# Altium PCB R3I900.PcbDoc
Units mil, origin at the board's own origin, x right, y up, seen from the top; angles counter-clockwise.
Board outline not stored, 2 copper layers (Top Layer, Bottom Layer); 27 components, 25 nets, 102 pads, 31 vias.
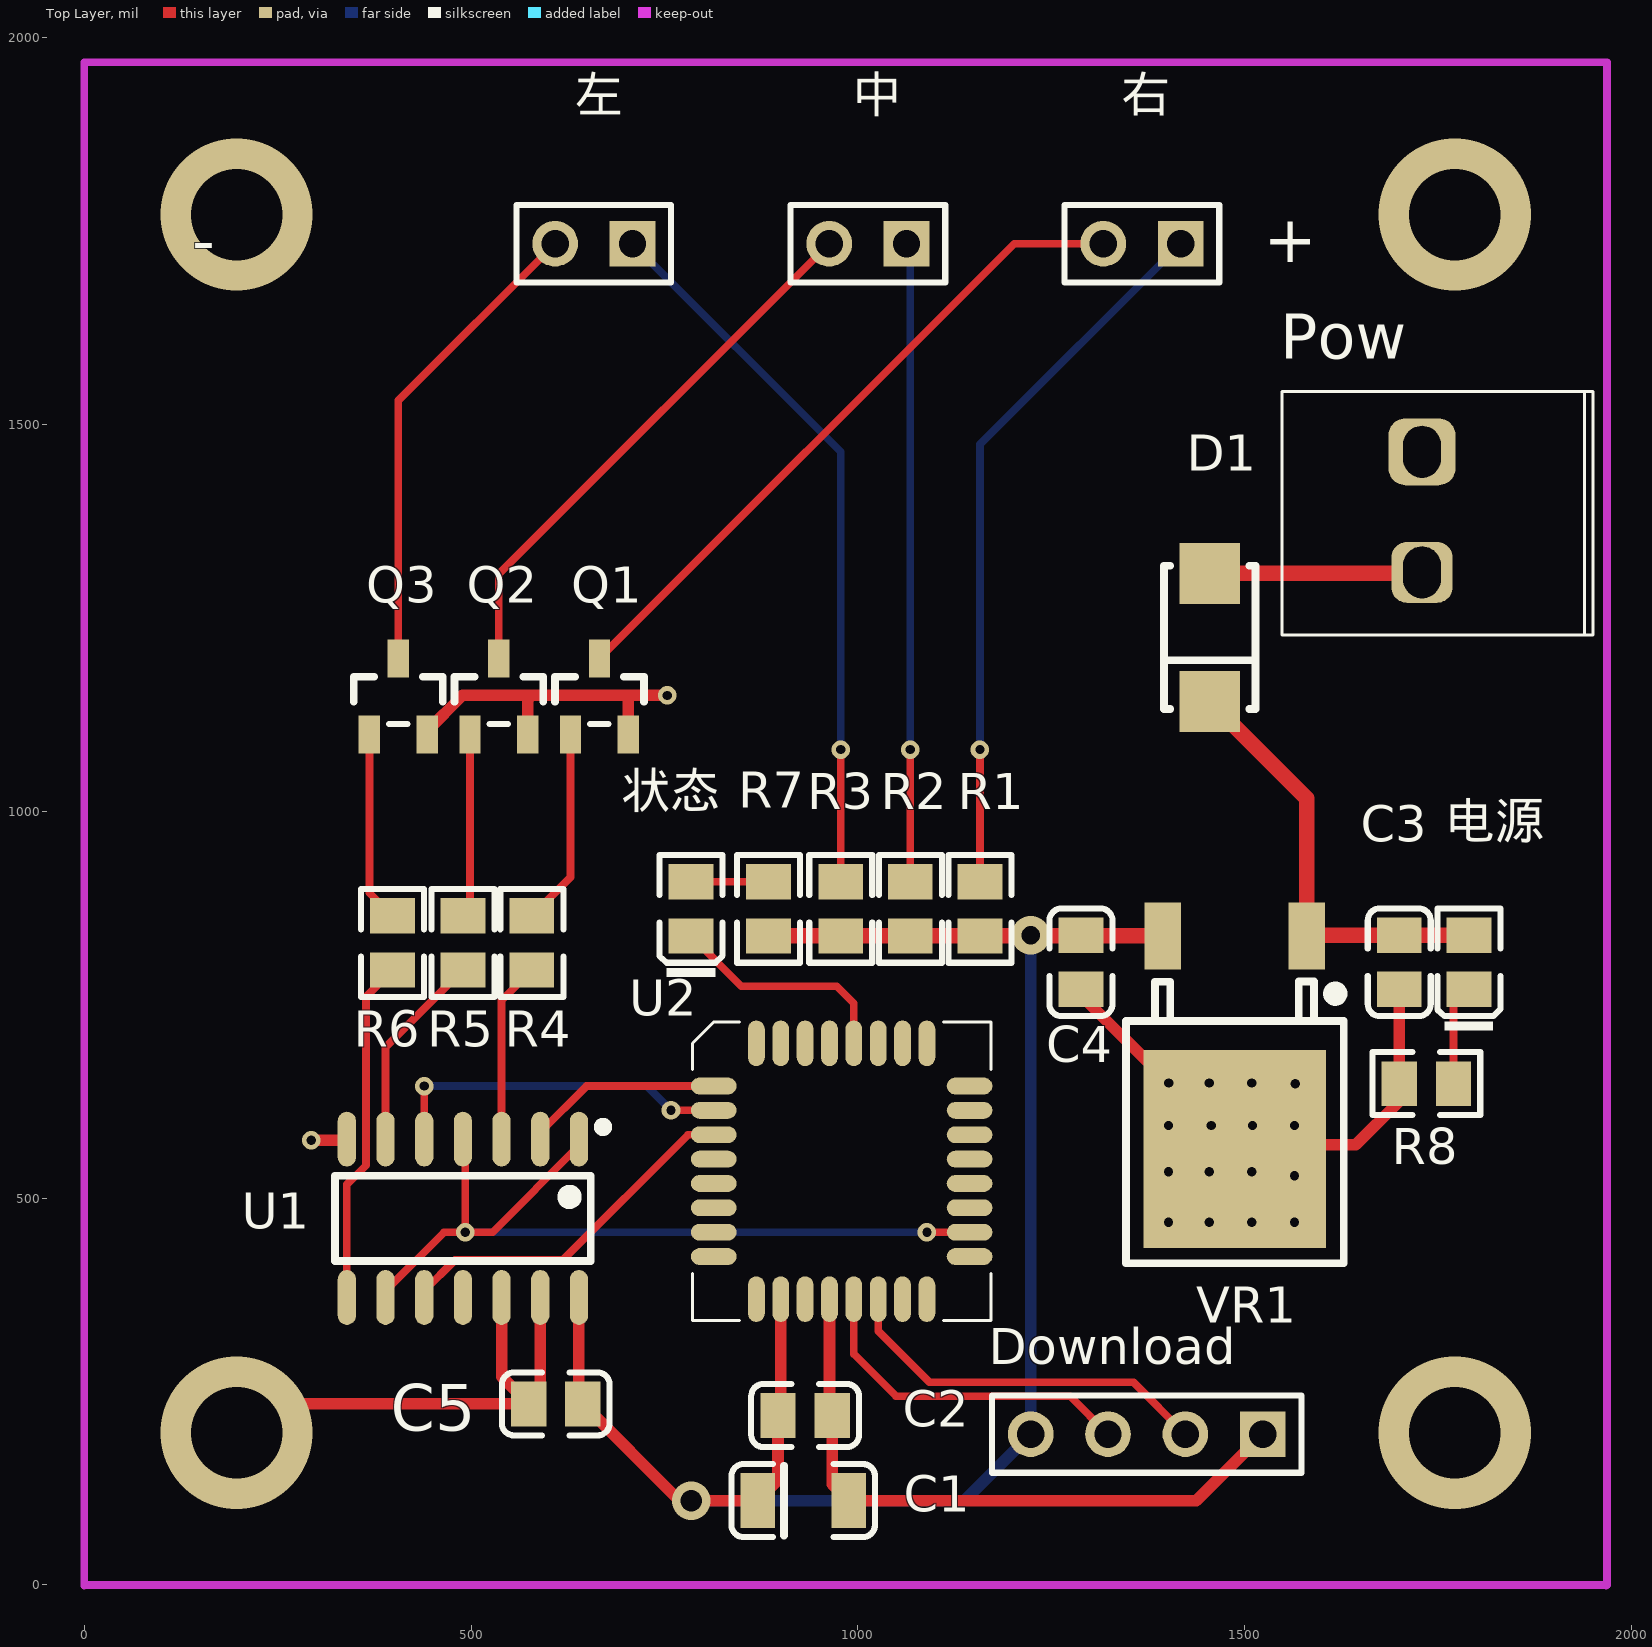
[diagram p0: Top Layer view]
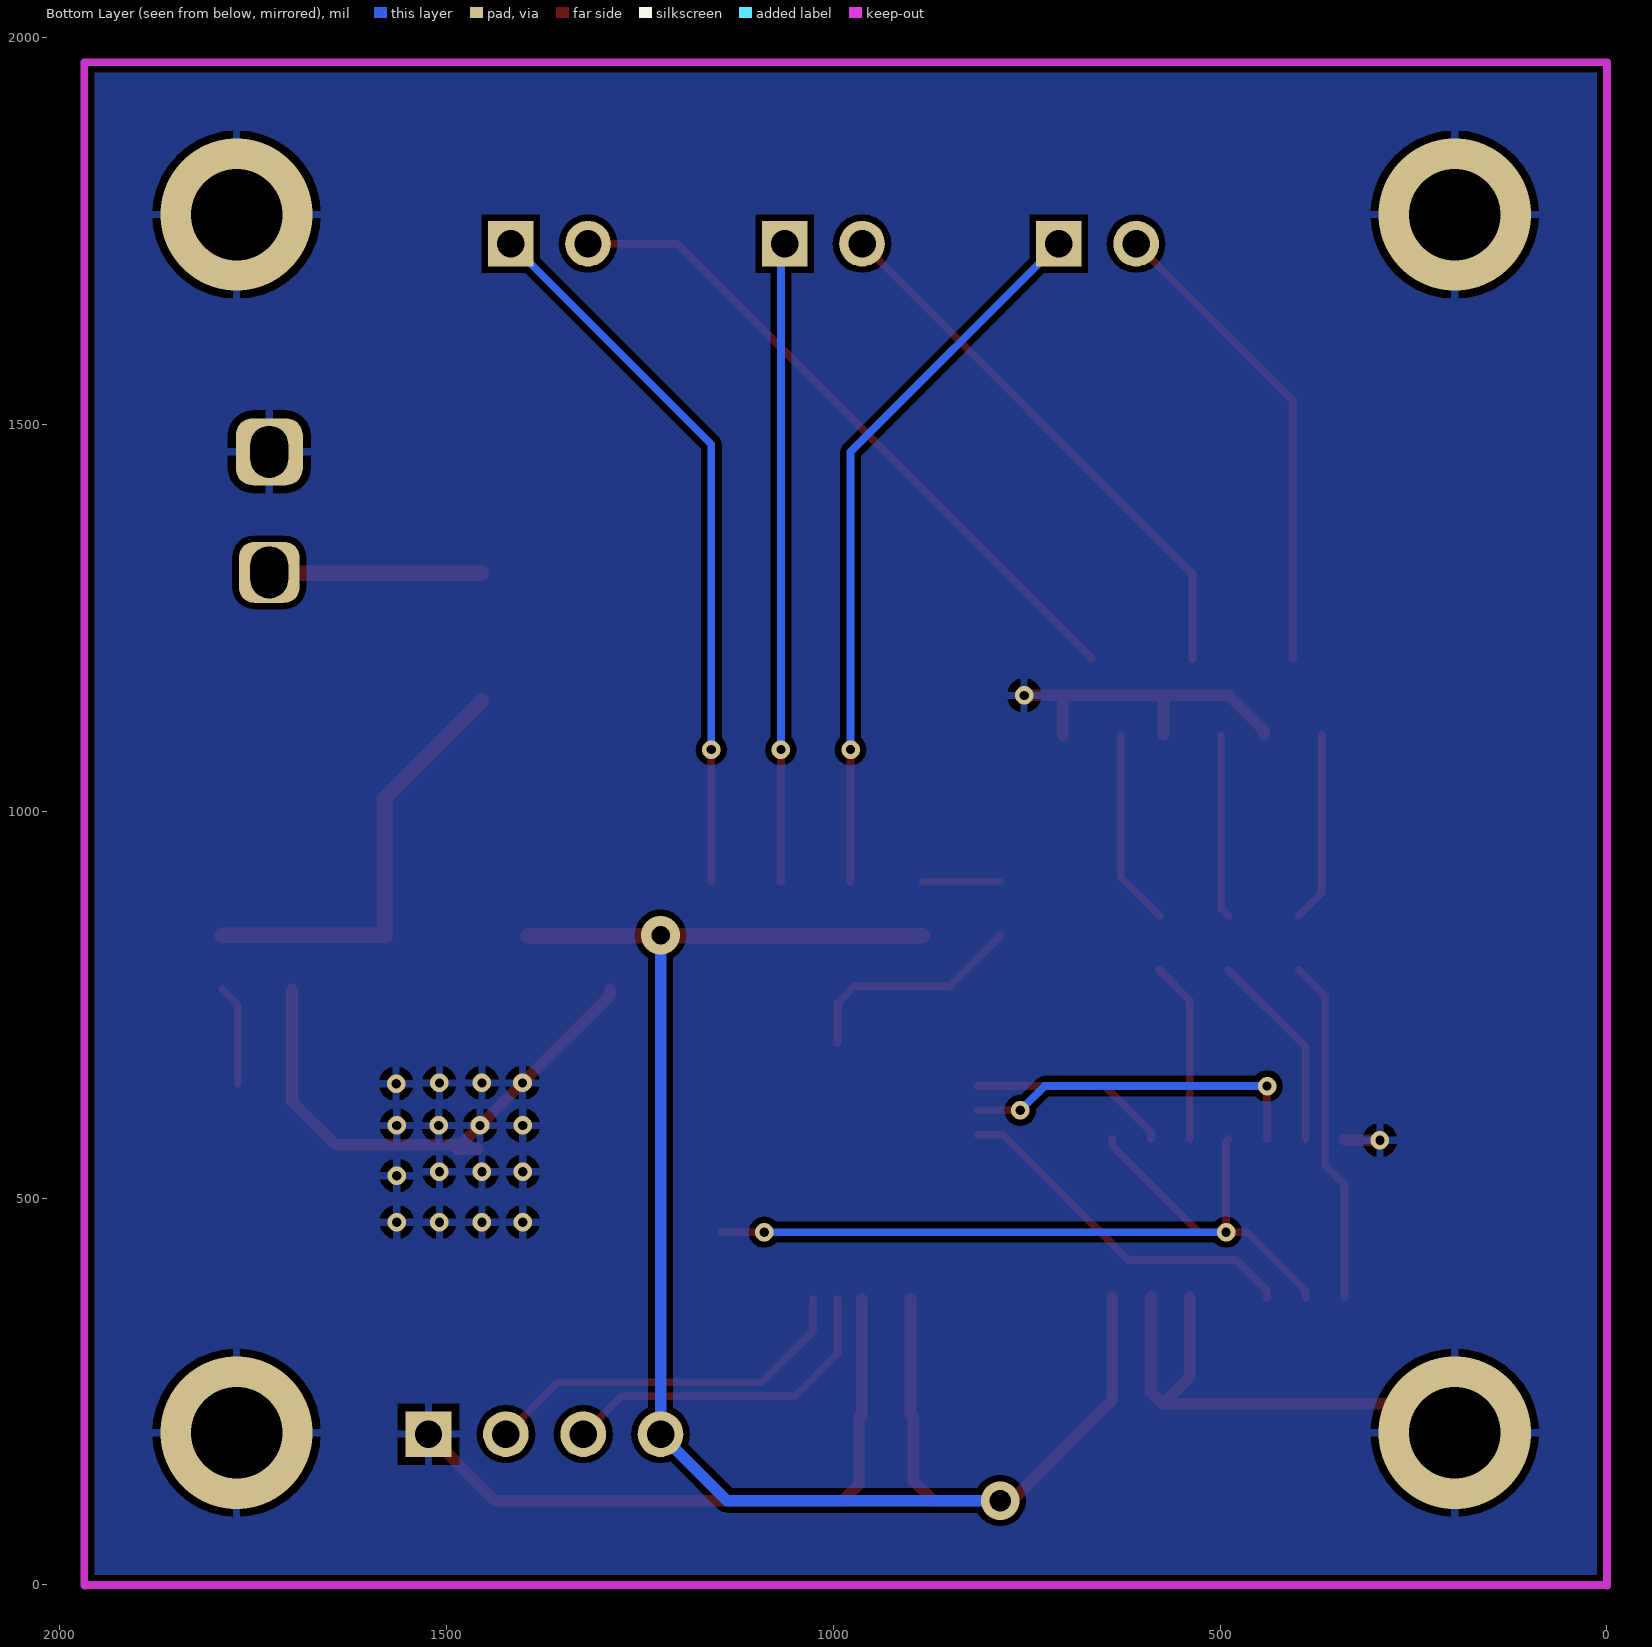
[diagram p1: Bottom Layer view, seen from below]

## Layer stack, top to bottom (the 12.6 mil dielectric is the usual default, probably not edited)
Top Solder: solder mask 0.4, Solder Resist, Dk 3.5
Top Layer: signal copper 1.4
Dielectric 1: dielectric 12.6, FR-4, Dk 4.8
Bottom Layer: signal copper 1.4
Bottom Solder: solder mask 0.4, Solder Resist, Dk 3.5

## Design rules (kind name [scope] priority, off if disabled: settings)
Clearance [All] p1: gap=8 ignorepadtopadclearanceinfootprint=FALSE
PolygonConnect [All] p1: connectstyle=Relief reliefconductorwidth=10 reliefentries=4 polygonreliefangle="90 Angle" airgapwidth=10
RoutingVias [All] p1: holewidth=28 width=50 viastyle="Through Hole" minholewidth=28 minwidth=50 maxholewidth=28 maxwidth=50
SolderMaskExpansion [All] p1: expansion=4
Width [All] p1: maxlimit=20 minlimit=8 preferedwidth=10
30 further rules are at their usual default settings.

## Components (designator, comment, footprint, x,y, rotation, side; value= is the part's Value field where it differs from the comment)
C1 "4.7uF (475) 10% 50V" LC-1206_C 929.45,109.06 r180 top locked
C2 "100nF(104) 10% 50V" LC-0805_C 931.85,219.06 r180 top locked
C3 "330nF (334) 10% 50V" LC-0805_C 1700,805 r90 top
C4 "100nF(104) 10% 50V" LC-0805_C 1288.5,805 r90 top locked
C5 "100nF(104) 10% 50V" LC-0805_C 609.45,234.06 r180 top locked
D1 "SS210" LC-SMA(DO-214AC)_S1 1455,1225 r90 top
Download "Header 4" HDR1X4 1523.5,195 r180 top (schematic designator Download1)
Pow "Header 2" "VH-2A - Circle Hole" 1729.41,1465 r270 top
Q1 "SS8050 Y1" LC-SOT-23(SOT-23-3) 665.94,1148.47 r270 top locked
Q2 "SS8050 Y1" LC-SOT-23(SOT-23-3) 535.94,1148.47 r270 top locked
Q3 "SS8050 Y1" LC-SOT-23(SOT-23-3) 405.94,1148.47 r270 top locked
R1 "100Ω (1000) ±1%" LC-0805_R 1157.91,874.06 r270 top locked
R2 "100Ω (1000) ±1%" LC-0805_R 1067.91,874.06 r270 top locked
R3 "100Ω (1000) ±1%" LC-0805_R 977.91,874.06 r270 top locked
R4 "1KΩ (1001) ±1%" LC-0805_R 578.5,830 r90 top locked
R5 "1KΩ (1001) ±1%" LC-0805_R 489.45,830 r90 top locked
R6 "1KΩ (1001) ±1%" LC-0805_R 398.5,830 r90 top locked
R7 "10KΩ (1002) ±1%" LC-0805_R 884.45,874.06 r90 top locked
R8 "10KΩ (1002) ±1%" LC-0805_R 1735,648.11 r0 top
U1 "74HC08D" LC-SOIC-14_150mil 489.45,474.06 r180 top locked
U2 "STC15F2K60S2_QFP32" LQFP32 813.74,645.04 r0 top locked
VR1 "L78M05ABDT-TR" LC-TO-252-2-180 1487.41,839.22 r270 top locked
中 "Header 2" HDR1X2 1062.99,1734.06 r180 top
右 "Header 2" HDR1X2 1417.32,1734.06 r180 top
左 "Header 2" HDR1X2 708.66,1734.06 r180 top
状态 "翠绿 0805" LC-0805_LED_S1 784.45,874.06 r90 top locked (schematic designator ״̬)
电源 "红灯 0805" LC-0805_LED_S1 1790,805 r90 top

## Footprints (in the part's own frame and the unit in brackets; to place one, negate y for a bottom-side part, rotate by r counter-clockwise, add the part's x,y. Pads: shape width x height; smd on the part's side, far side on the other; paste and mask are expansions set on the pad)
HDR1X2 [mm] "Connector; Header; 2 Position"
  rect 1.5x1.5 hole 0.9: 1(0,0)
  round 1.5 hole 0.9: 2(2.54,0)
  silkscreen extent -1.27,-1.27 3.81,1.27
HDR1X4 [mm] "Connector; Header; 4 Position"
  rect 1.5x1.5 hole 0.9: 1(0,0)
  round 1.5 hole 0.9: 2(2.54,0) 3(5.08,0) 4(7.62,0)
  silkscreen extent -1.27,-1.27 8.89,1.27
LC-0805_C [mm]
  rect 1.16x1.47 smd: 1(-0.89,0) 2(0.89,0)
  silkscreen extent -1.77,-1.04 1.77,1.04, body extent -1,-0.62 1,0.63, height 0.77
LC-0805_LED_S1 [mm]
  rect 1.16x1.47 smd: A(0.89,0) K(-0.89,0)
  silkscreen extent -2.24,-1.03 1.77,1.03, body extent -1.01,-0.62 1.01,0.62, height 1.1
LC-0805_R [mm]
  rect 1.16x1.47 smd: 1(-0.89,0) 2(0.89,0)
  silkscreen extent -1.77,-1.03 1.77,1.04, body extent -1,-0.62 1,0.63, height 0.49
LC-1206_C [mm]
  rect 1.13x1.8 smd: 1(-1.49,0) 2(1.49,0)
  silkscreen extent -2.36,-1.2 2.35,1.2, body extent -1.6,-0.81 1.6,0.79, height 1
LC-SMA(DO-214AC)_S1 [mm]
  rect 2x2 smd: 1(2.1,0) 2(-2.1,0)
  silkscreen extent -2.35,-1.5 2.35,1.5
LC-SOIC-14_150mil [mm]
  oval 0.6x1.8 smd: 1(-3.81,-2.6) 2(-2.54,-2.6) 3(-1.27,-2.6) 4(0,-2.6) 5(1.27,-2.6) 6(2.54,-2.6) 7(3.81,-2.6) 8(3.81,2.6) 9(2.54,2.6) 10(1.27,2.6) 11(0,2.6) 12(-1.27,2.6) 13(-2.54,2.6) 14(-3.81,2.6)
  silkscreen extent -4.75,-3.15 4.2,1.4
LC-SOT-23(SOT-23-3) [mm]
  rect 1.25x0.7 smd: 1(1.25,-0.95) 2(1.25,0.95) 3(-1.25,0)
  silkscreen extent -0.65,-1.46 0.9,1.46, body extent -1.5,-1.5 1.5,1.5, height 1.3
LC-TO-252-2-180 [mm] "180度编带包装"
  rect 2.2x1.2 smd: 1(0,2.361) 3(0.004,-2.361)
  rect 6.5x6 smd: 2(7,0)
  silkscreen extent 1.5,-3.57 10.75,3.57, body extent -0.2,-3.27 9.74,3.27, height 2.44
LQFP32 [mm]
  oval 1.5x0.55 smd: 1(0,0) 2(0,-0.8) 3(0,-1.6) 4(0,-2.4) 5(0,-3.2) 6(0,-4) 7(0,-4.8) 8(0,-5.6) 17(8.4,-5.6) 18(8.4,-4.8) 19(8.4,-4) 20(8.4,-3.2) 21(8.4,-2.4) 22(8.4,-1.6) 23(8.4,-0.8) 24(8.4,0)
  oval 0.55x1.5 smd: 9(1.4,-7) 10(2.2,-7) 11(3,-7) 12(3.8,-7) 13(4.6,-7) 14(5.4,-7) 15(6.2,-7) 16(7,-7) 25(7,1.4) 26(6.2,1.4) 27(5.4,1.4) 28(4.6,1.4) 29(3.8,1.4) 30(3,1.4) 31(2.2,1.4) 32(1.4,1.4)
  silkscreen extent -0.7,-7.7 9.1,2.1
"VH-2A - Circle Hole" [mm] "Header 2 use for Power"
  rrect50% 2.2x2.2 hole 1.24 slot 1.7 at 0 deg: 1(0,0)
  rrect50% 2x2 hole 1.24 slot 1.7 at 0 deg: 2(3.96,0)
  silkscreen extent -1.98,-4.6 6.02,5.61

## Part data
C1: library part "1206 4.7uF (475) 10% 50V", "贴片电容", Package=1206, SuppliersPartNumber=C29823
C2 C4 C5: library part "0805 100nF(104) 10% 50V", "贴片电容", Package=0805, SuppliersPartNumber=C49678
C3: library part "0805 330nF (334) 10% 50V", "贴片电容", Package=0805, SuppliersPartNumber=C1740
D1: library part "SMA(DO-214AC) SS210", "二极管", Package=SMA(DO-214AC), SuppliersPartNumber=C14996
Download: "Header, 4-Pin"
Pow: "贴片2p座"
Q1 Q2 Q3: library part "SOT-23 SS8050 Y1", "三极管", Package=SOT-23, SuppliersPartNumber=C2150
R1 R2 R3: library part "0805 100Ω (1000) 1%", "贴片电阻", Package=0805, SuppliersPartNumber=C17408
R4 R5 R6: library part "0805 1KΩ (1001) 1%", "贴片电阻", Package=0805, SuppliersPartNumber=C17513
R7 R8: library part "0805 10KΩ (1002) 1%", "贴片电阻", Package=0805, SuppliersPartNumber=C17414
U1: "74系列逻辑芯片", Package=SOIC-16_150mil, SuppliersPartNumber=C5602
VR1: library part "TO-252-2 L78M05ABDT-TR", "低压差线性稳压(LDO)", Package=TO-252-2, SuppliersPartNumber=C58069
中 右 左: "Header, 2-Pin"
状态: library part "0805 翠绿", "发光二极管", Package=0805, SuppliersPartNumber=C2297
电源: library part "0805 红灯", "发光二极管", Package=0805, SuppliersPartNumber=C2295

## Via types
v1: diameter 24, hole 12, Top Layer to Bottom Layer, 25 vias
v2: diameter 196.85, hole 118.11, Top Layer to Bottom Layer, 4 vias
v3: diameter 50, hole 24, Top Layer to Bottom Layer, 1 vias
v4: diameter 50, hole 28, Top Layer to Bottom Layer, 1 vias

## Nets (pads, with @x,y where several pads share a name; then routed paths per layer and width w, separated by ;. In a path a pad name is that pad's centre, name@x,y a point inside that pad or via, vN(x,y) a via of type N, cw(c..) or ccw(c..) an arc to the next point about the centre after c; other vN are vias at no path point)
38K: U1.1 U1.4 U1.9 U2.18 | length 1118.6
  Top Layer w10: U1.9 389.45,380.4 465.11,456.06 v1(492.44,456.06) ; U1.4 492.44,573.43 v1(492.44,456.06) ; U1.1 639.45,567.71 527.8,456.06 v1(492.44,456.06) ; v1(1089.33,456.06) U2.18
  Bottom Layer w10: v1(492.44,456.06) v1(1089.33,456.06)
+5: C1.2 C2.2 C4.2 C5.1 Download.4 R1.2 R2.2 R3.2 R7.1 U1.14 U2.10 VR1.3 | length 2318.7
  Top Layer w15: U1.14 639.45,239.1 C5.1 769.49,109.06 v4(784.45,109.06) C1.2 896.81,135.08 C2.2 ; C2.2@900.35,219.06 U2.10
  Top Layer w20: R7.1 884.53,839.1 1254.45,839.1 ; 1254.45,839.22 1394.28,839.22 VR1.3
  Bottom Layer w15: v4(784.45,109.06) 1137.56,109.06 Download.4 v3(1223.5,840)
+12: C3.2 D1.2 VR1.1 电源.A | length 565
  Top Layer w20: D1.2 1580.38,1016.95 VR1.1 1581.2,840.04 C3.2 电源.A
GND: C1.1 C2.1 C3.1 C4.1 C5.2 Download.1 Pow.1 Q1.2 Q2.2 Q3.2 R8.1 U1.7 U1.12 U1.13 U2.12 VR1.2 | length 2717.9
  Top Layer w10: VR1.2@1481.99,569.05 VR1.2@1487.41,569.05
  Top Layer w15: v2(196.85,196.85) 234.06,234.06 C5.2 ; v1(293.5,575) 338.03,575 U1.7 ; Q3.2 443.35,1104.36 488.98,1150 578.5,1150 ; U1.12 539.45,269.02 C5.2 ; Q2.2 573.35,1144.84 578.5,1150 ; U1.13 589.45,249.1 C5.2 ; Q1.2 703.35,1145.16 698.5,1150 ; v1(753.5,1150) 698.5,1150 ; C2.1@963.35,219.06 U2.12 ; C2.1 966.89,130.28 C1.1 1437.56,109.06 Download.1 ; C4.1 1288.5,762.54 v1(1401.99,649.06) v1(1456.99,594.06) 1481.99,569.05 VR1.2 VR1.2@1459.83,563.63 ; VR1.2@1487.41,569.05 1643.94,568.98 1700,625.04 1700,715 C3.1 ; 578.5,1150 698.5,1150
  other v1: 1401.77,469.06 1454.45,469.06 1509.45,469.06 1564.45,469.06 1564.45,529.06 1401.77,534.06 1454.45,534.06 1509.45,534.06 1401.77,594.06 1510.39,594.06 1564.45,594.06 1565.39,648.11 1454.45,649.06 1509.45,649.06
  other v2: 1771.65,196.85 196.85,1771.65 1771.65,1771.65
Left: U1.2 U2.1 | length 257.8
  Top Layer w10: U1.2 589.45,585.13 649.36,645.04 U2.1
Middle: U1.5 U2.2 | length 455.9
  Top Layer w10: U1.5 v1(439.45,645) ; v1(758.5,613.54) U2.2
  Bottom Layer w10: v1(439.45,645) 727.05,645 v1(758.5,613.54)
NetD1_1: D1.1 Pow.2 | length 292.6
  Top Layer w20: D1.1 1727.99,1307.68 Pow.2 Pow.2@1711.81,1309.09
NetQ1_1: Q1.1 R4.2 | length 254.9
  Top Layer w10: R4.2 628.54,915.08 Q1.1
NetQ1_3: Q1.3 右.2 | length 873.6
  Top Layer w10: Q1.3 1202.32,1734.06 右.2
NetQ2_1: Q2.1 R5.2 | length 238
  Top Layer w10: R5.2 498.54,874.13 Q2.1
NetQ2_3: Q2.3 中.2 | length 713.3
  Top Layer w10: Q2.3 535.94,1307.01 中.2
NetQ3_1: Q3.1 R6.2 | length 246.6
  Top Layer w10: Q3.1 368.54,895 R6.2
NetQ3_3: Q3.3 左.2 | length 620.3
  Top Layer w10: Q3.3 405.94,1531.34 左.2
NetR1_1: R1.1 右.1 | length 932.4
  Top Layer w10: R1.1 v1(1157.91,1080)
  Bottom Layer w10: v1(1157.91,1080) 1157.91,1474.65 右.1
NetR2_1: R2.1 中.1 | length 827
  Top Layer w10: R2.1 v1(1067.91,1080)
  Bottom Layer w10: 中.1 1067.91,1729.13 v1(1067.91,1080)
NetR3_1: R3.1 左.1 | length 936.5
  Top Layer w10: R3.1 v1(977.91,1080)
  Bottom Layer w10: 左.1 977.91,1464.8 v1(977.91,1080)
NetR4_1: R4.1 U1.3 | length 234.7
  Top Layer w10: U1.3 539.45,755.9 R4.1
NetR5_1: R5.1 U1.6 | length 260
  Top Layer w10: U1.6 389.45,694.96 R5.1
NetR6_1: R6.1 U1.8 | length 447.7
  Top Layer w10: U1.8 339.45,517.71 364.26,542.52 364.26,760.72 R6.1
NetR7_2: R7.2 状态.A | length 100
  Top Layer w10: 状态.A R7.2
NetR8_2: R8.2 电源.K | length 130.1
  Top Layer w10: R8.2 1770.04,750 电源.K
NetU2_28: U2.28 状态.K | length 298.3
  Top Layer w10: 状态.K 849.41,774.06 972.87,774.06 994.84,752.09 U2.28
Right: U1.10 U2.3 | length 466.5
  Top Layer w10: U1.10 439.45,380.4 479.17,420.13 618.63,420.13 780.55,582.05 U2.3
RX: Download.3 U2.13 | length 442.4
  Top Layer w10: U2.13 994.84,298.66 1049.45,244.06 1274.45,244.06 Download.3
TX: Download.2 U2.14 | length 493.5
  Top Layer w10: U2.14 1026.34,328.37 1092.65,262.06 1356.45,262.06 Download.2
pads on no net: U1.11 U2.4 U2.5 U2.6 U2.7 U2.8 U2.9 U2.11 U2.15 U2.16 U2.17 U2.19 U2.20 U2.21 U2.22 U2.23 U2.24 U2.25 U2.26 U2.27 U2.29 U2.30 U2.31 U2.32

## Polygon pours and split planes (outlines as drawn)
GND on Bottom Layer "Bottom Layer-GND" (solid, pour order 4): 0,1967.56 1968.5,1967.56 1968.5,0 1969.45,-0.94 0,-0.94

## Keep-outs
Keep-Out Layer:
  lines w10: 1967.56,-0.94 1968.5,0 ; 1968.5,0 0,0 0,1968.5 1968.5,1968.5 1968.5,0 ; 0,-0.94 0,-0.94

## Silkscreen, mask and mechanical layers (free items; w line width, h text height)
Top Overlay:
  lines w10: 904.45,64.06 904.45,154.06
  text "+" at 1525,1710 h60
  text "-" at 139.45,1709.06 h60

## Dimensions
0,0 to 0,1968.5 on Top Overlay
0,0 to 1968.5,0 on Top Overlay
962.99,1734.06 to 708.66,1734.06 on Top Overlay
1062.99,1734.06 to 1317.32,1734.06 on Top Overlay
